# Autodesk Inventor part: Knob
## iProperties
Shininess: 64.0
Length Units: 11272
Angle Units: 11279
Time Units: 11290
Mass Units: 11286
Length Display Precision: 3
Angle Display Precision: 2
Compacted: True
Part Number: Knob
Document SubType Name: Modeling
Created: 2003-08
Designer: FT User
Manufacturer: Standard
Standards Organization: Custom
Density: 0.0
Volumn: 0.0
Area: 0.0
PropertySet Name: Model Information
Control State: 0
Master: False
Checked Out: False
Author: FT User
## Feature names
1. Extrusion1
2. Extrusion2
